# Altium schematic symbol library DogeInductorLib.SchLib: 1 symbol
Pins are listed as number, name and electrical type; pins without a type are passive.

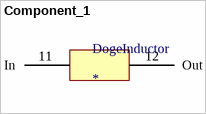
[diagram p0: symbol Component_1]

## Component_1
designator DogeInductor
Doge
footprint inductor
pins: 11 In, 12 Out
